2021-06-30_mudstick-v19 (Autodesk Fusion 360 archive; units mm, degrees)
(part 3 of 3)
component_insert "Component Insert62"
joint "Assemble59" alignAngle 0 alignOffsetX 0 alignOffsetY 0 alignOffsetZ 0
component_insert "Component Insert63"
joint "Assemble60" alignAngle 0 alignOffsetX 0 alignOffsetY 0 alignOffsetZ 0
component_insert "Component Insert64"
joint "Assemble61" alignAngle 0 alignOffsetX 0 alignOffsetY 0 alignOffsetZ 0
component_insert "Component Insert65"
joint "Assemble62" alignAngle 0 alignOffsetX 0 alignOffsetY 0 alignOffsetZ 0
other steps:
fillet "Extrude176" sketch "Plan" ProfileOffset 0 Side1Offset 0 TaperAngle 0
step "OffsetFaces11" distance -0.075
fillet "Extrude177" sketch "Plan" ProfileOffset 0 Side1Offset 0 TaperAngle 0
step "OffsetFaces10" distance -0.075
step "OffsetFaces12" distance -0.075
fillet "Extrude165" sketch "Plan" ProfileOffset 0 Side1Offset 0 TaperAngle 0
fillet "Extrude166" sketch "Plan" ProfileOffset 0 Side1Offset 0 TaperAngle 0
fillet "Extrude167" sketch "Plan" ProfileOffset 0 Side1Offset 0 TaperAngle 0
fillet "Extrude168" sketch "Plan" ProfileOffset 0 Side1Offset 0 TaperAngle 0
fillet "Extrude169" Side1Offset 0 TaperAngle 0
fillet "Extrude170" TaperAngle 0
step "OffsetFaces9" distance -0.075
fillet "Extrude171" Side1Offset 0 TaperAngle 0
fillet "Extrude172" ProfileOffset 0 Side1Offset 0 TaperAngle 0
fillet "Extrude173" Side1Offset 0 TaperAngle 0
fillet "Extrude174" sketch "Elevation" Side1Offset 0 TaperAngle 0
fillet "Extrude175" sketch "Elevation" Side1Offset 0 TaperAngle 0
fillet "Extrude178" ProfileOffset 0 Side1Offset 0 TaperAngle 0
step "Fillet" Radius 1.05 (= "od_mintool / 2")
step "JointOrigin46"
step "Component Insert50"
step "Assemble50" alignAngle 0 alignOffsetX 0 alignOffsetY 0 alignOffsetZ 0
step "JointOrigin47"
step "Component Insert51"
step "Assemble51" alignAngle 90 alignOffsetX 0 alignOffsetY 0 alignOffsetZ 0
step "JointOrigin48"
joint_origin "JointOrigin52"
joint_origin "JointOrigin53"
joint_origin "JointOrigin54"
joint_origin "JointOrigin55"
joint_origin "JointOrigin56"
joint_origin "JointOrigin57"
joint_origin "JointOrigin58"
joint_origin "JointOrigin59"

design "Hotplate Pogo Drop"
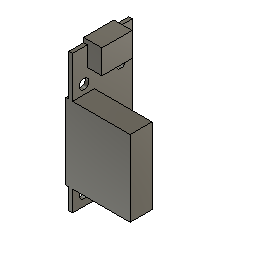
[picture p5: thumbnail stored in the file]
sketch "Sketch1" plane through (0, 0, 0) normal (1, 0, 0) x axis (0, 1, 0)
  line L1 (26, 0) -> (0, 0)
  line L2 (26, 60) -> (26, 0)
  line L3 (0, 60) -> (26, 60)
  line L4 (0, 0) -> (0, 60)
  line L5 (15.5, 49.5) -> (10.5, 49.5)
  line L6 (15.5, 1.5) -> (15.5, 49.5)
  line L7 (10.5, 1.5) -> (15.5, 1.5)
  line L8 (10.5, 49.5) -> (10.5, 1.5)
  line L9 (15.5, 1.5) -> (10.5, 49.5)
  line L10 (13, 0) -> (13, 25.5)
  line L11 (26, 25.5) -> (13, 25.5)
  line L12 (5, 5) -> (5, 46)
  line L13 (21, 5) -> (5, 5)
  line L14 (21, 46) -> (21, 5)
  line L15 (9.5, 42) -> (0, 42)
  line L16 (9.5, 9) -> (9.5, 42)
  line L17 (0, 9) -> (9.5, 9)
  line L18 (21, 46) -> (5, 46)
  line L19 (19.55, 51.5) -> (6.45, 51.5)
  line L20 (19.55, 62) -> (19.55, 51.5)
  line L21 (6.45, 62) -> (19.55, 62)
  line L22 (6.45, 51.5) -> (6.45, 62)
  line L23 (13, 49.5) -> (13, 51.5)
  circle C1 centre (5, 46) radius 2.125
  circle C2 centre (5, 5) radius 2.125
  circle C3 centre (21, 46) radius 2.125
  circle C4 centre (21, 5) radius 2.125
  point P1 (0, 0)
  point P2 (0, 0)
  point P10 (13, 25.5)
  point P11 (13, 0)
  point P13 (5, 46)
  point P17 (5, 46)
  point P14 (5, 5)
  point P18 (5, 5)
  point P19 (5, 5)
  point P16 (21, 5)
  point P20 (21, 5)
  point P21 (21, 5)
  point P15 (21, 46)
  point P22 (21, 46)
  point P23 (0, 42)
  point P26 (0, 9)
  point P27 (9.5, 25.5)
  point P28 (5, 46)
  point P29 (21, 46)
  point P34 (13, 51.5)
  point P35 (13, 49.5)
  point P3 (26, 0)
  point P5 (0, 60)
  point P6 (10.5, 49.5)
  point P9 (10.5, 1.5)
  point P7 (15.5, 49.5)
  point P24 (9.5, 42)
  point P25 (9.5, 9)
  point P32 (19.55, 62)
  point P33 (6.45, 62)
  horizontal L1
  vertical L2
  horizontal L3
  vertical L4
  coincident P1 P2
  horizontal L5
  vertical L6
  horizontal L7
  vertical L8
  midpoint L9 P10
  coincident L1 P11
  perpendicular L1 L10
  horizontal L11
  equal C3 C4
  equal C1 C4
  equal C1 C2
  coincident P13 P17
  vertical L12
  coincident P14 P18
  coincident P14 P19
  coincident P16 P20
  horizontal L13
  coincident P16 P21
  perpendicular L13 L14
  coincident P15 P22
  coincident L4 P23
  perpendicular L4 L15
  perpendicular L15 L16
  coincident L4 P26
  perpendicular L4 L17
  midpoint L16 P27
  coincident L11 P27
  coincident P13 P28
  coincident P15 P29
  horizontal L18
  horizontal L19
  vertical L20
  horizontal L21
  vertical L22
  midpoint L19 P34
  midpoint L5 P35
  vertical L23
  dimension "d1" distance P2 P3 = 26
  dimension "d2" distance P2 P5 = 60
  dimension "d4" distance P1 L10 = 13
  dimension "d5" distance P6 P9 = 48 (= "( 24 * 2 ) * 1 mm")
  dimension "d6" distance P6 P7 = 5
  dimension "d7" diameter C1 = 4.25
  dimension "d9" distance L4 P13 = 5
  dimension "d23" distance P23 P24 = 9.5
  dimension "d24" distance P24 P25 = 33
  dimension "d25" distance L1 P27 = 25.5
  dimension "d26" distance L3 L18 = 14
  dimension "d27" distance L1 P14 = 5
  dimension "d28" distance L10 L14 = 8
  dimension "d29" distance P32 P33 = 13.1
  dimension "d30" distance L3 L21 = 2
  dimension "d31" distance P7 L19 = 2
extrude "Extrude1" new body sketch "Sketch1" profile of L1 L2 L3 L4 L5 L6 L7 L8 C1 C2 C3 C4 along normal blind 1.6
extrude "Extrude2" add sketch "Sketch1" profile of L5 L6 L7 L8 against normal blind 0.5
extrude "Extrude3" sketch "Sketch1" profile of L4 L15 L16 L17 blind 25
extrude "Extrude4" add sketch "Sketch1" profile of L4 L15 L16 L17 against normal blind 1.2448 (magnitude of "-0.112 in + 1.6 mm")
extrude "Extrude5" add sketch "Sketch1" profile of L3 L19 L20 L21 L22 to an object offset 6.3

design "2298K420_METRIC QUICK-GRIP SCREW-CLAMP BUSHING"
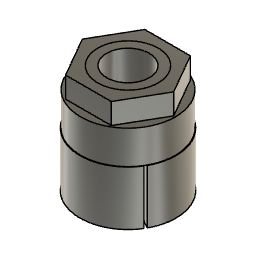
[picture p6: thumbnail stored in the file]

design "N17 48mm"
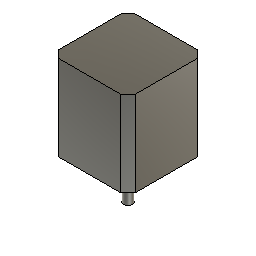
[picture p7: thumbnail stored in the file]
sketch "Sketch1" plane through (0, 0, 0) normal (0, 0, 1) x axis (1, 0, 0)
  line L1 (-21.6, 21.6) -> (21.6, 21.6)
  line L2 (-21.6, -21.6) -> (-21.6, 21.6)
  line L3 (21.6, 21.6) -> (21.6, -21.6)
  line L4 (21.6, 21.6) -> (21.6, 21.6)
  line L5 (-21.6, -21.6) -> (21.6, 21.6)
  line L6 (21.6, -21.6) -> (-21.6, 21.6)
  line L7 (15.5, 15.5) -> (-15.5, 15.5)
  line L8 (15.5, -15.5) -> (15.5, 15.5)
  line L9 (-15.5, -15.5) -> (15.5, -15.5)
  line L10 (-15.5, 15.5) -> (-15.5, -15.5)
  circle C1 centre (0, 0) radius 11
  circle C2 centre (-15.5, 15.5) radius 1.5
  circle C3 centre (-15.5, -15.5) radius 1.5
  circle C4 centre (15.5, -15.5) radius 1.5
  circle C5 centre (15.5, 15.5) radius 1.5
  circle C6 centre (0, 0) radius 2.5
  point P6 (0, 0)
  point P1 (0, 0)
  point P7 (0, 0)
  point P10 (15.5, -15.5)
  point P8 (-15.5, 15.5)
  point P9 (15.5, 15.5)
  point P12 (-15.5, 15.5)
  point P11 (-15.5, -15.5)
  point P13 (-15.5, -15.5)
  point P14 (15.5, -15.5)
  point P15 (15.5, 15.5)
  point P2 (21.6, 21.6)
  point P3 (-21.6, 21.6)
  perpendicular L1 L2
  parallel L1 L3
  parallel L2 L4
  horizontal L1
  coincident L5 P6
  coincident L6 P6
  coincident P1 P6
  equal L1 L2
  coincident P6 P7
  horizontal L7
  vertical L8
  horizontal L9
  vertical L10
  coincident L6 P10
  coincident L6 P8
  coincident L5 P9
  coincident P8 P12
  coincident P11 P13
  coincident P10 P14
  coincident P9 P15
  equal C2 C5
  equal C2 C3
  equal C2 C4
  concentric C1 C6
  dimension "d1" distance P2 P3 = 43.2
  dimension "d2" diameter C1 = 22
  dimension "d3" distance P8 P9 = 31
  dimension "d4" diameter C2 = 3
  dimension "d5" diameter C6 = 5
extrude "Extrude1" new body sketch "Sketch1" profile of L1 L2 L3 L4 C1 C2 C3 C4 C5 C6 along normal blind 48
extrude "Extrude2" cut sketch "Sketch1" profile of C2 C3 C4 C5 along normal blind 5
extrude "Extrude3" add sketch "Sketch1" profile of C1 C6 against normal blind 2
extrude "Extrude4" add sketch "Sketch1" profile of C6 against normal blind 24
chamfer "Chamfer1" distance 4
